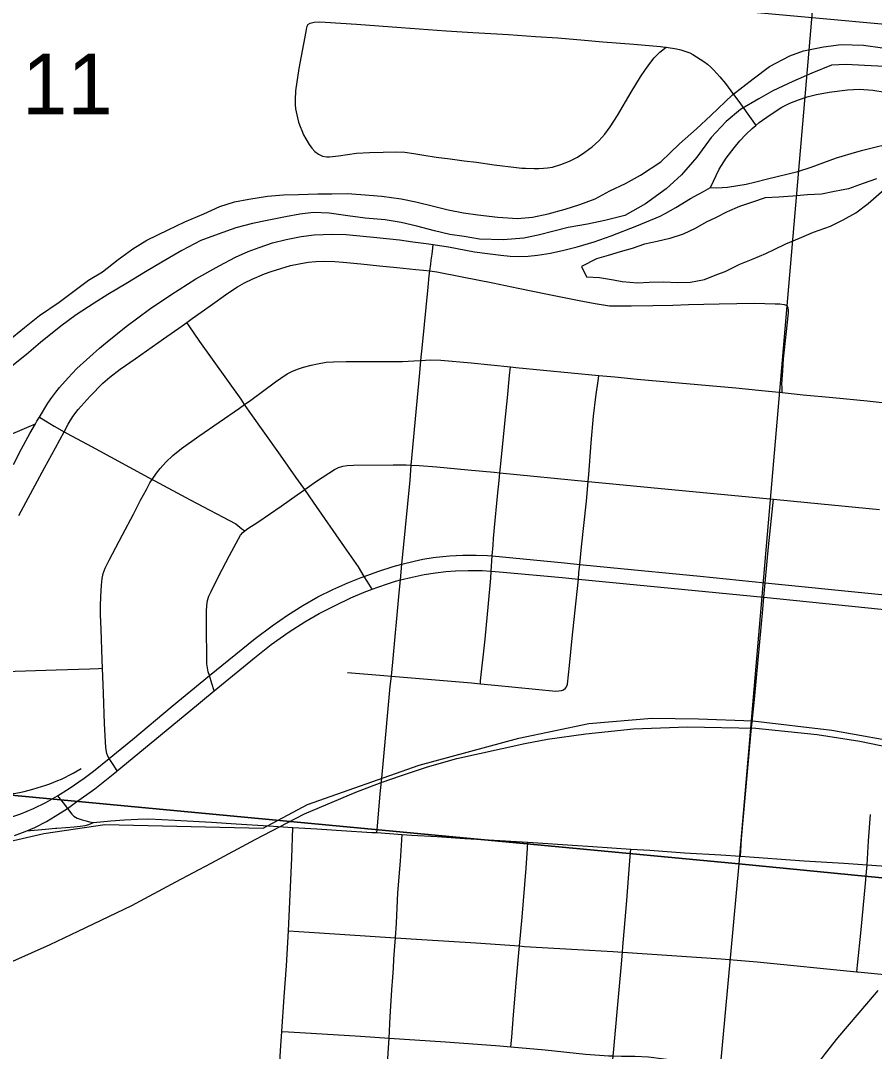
# Model space of a CAD drawing. Extents: x 0 to 1134, y 0 to 440.
# Drawn here: x 509.08 to 526.69, y 232.84 to 254.12 of the extents above; entities that cross this region are included whole.
import ezdxf

# ---------------------------------------------------------------- set-up
doc = ezdxf.new("R2010")
doc.units = 0
for name, color, linetype in [('Default', 7, 'Continuous'), ('GM_X_City_Street', 7, 'Continuous'), ('GM_X_County_Road', 7, 'Continuous'), ('GM_X_Major_River', 7, 'Continuous'), ('GM_X_Minor_Lake', 7, 'Continuous'), ('GM_X_Rail_Line', 7, 'Continuous'), ('GM_X_Section', 7, 'Continuous'), ('GM_X_Section_Text', 7, 'Continuous'), ('GM_X_State_Route', 7, 'Continuous'), ('GM_X_US_Route', 7, 'Continuous')]:
    doc.layers.add(name, color=color, linetype=linetype)

msp = doc.modelspace()

# ---------------------------------------------------------------- linework, layer by layer
at = {"layer": 'Default'}
for points in [[(539, 235.237), (539, 265.438), (526.475, 266.717), (523.893, 236.716)], [(539, 205.4), (539, 235.237), (523.893, 236.716), (521.182, 207.228)]]:
    msp.add_lwpolyline(points, close=True, dxfattribs=at)
at = {"layer": 'GM_X_City_Street'}
for points in [[(515.002, 254.042), (515.049, 254.066), (515.13, 254.086), (515.241, 254.096), (515.36, 254.088), (516.006, 254.046), (516.93, 253.978), (517.484, 253.937), (517.854, 253.91), (518.409, 253.875), (518.779, 253.854), (519.145, 253.832), (519.7, 253.795), (520.161, 253.763), (520.711, 253.721), (521.091, 253.684), (521.732, 253.637), (522.282, 253.585), (522.374, 253.576), (522.399, 253.572)], [(515.002, 254.042), (514.982, 254), (514.97, 253.945), (514.96, 253.894), (514.816, 253.132), (514.746, 252.671), (514.739, 252.485), (514.741, 252.392), (514.751, 252.299), (514.786, 252.116), (514.812, 252.027), (514.844, 251.939), (514.875, 251.852), (514.916, 251.763), (514.96, 251.679), (515.032, 251.563), (515.084, 251.487), (515.148, 251.419), (515.222, 251.364), (515.306, 251.325), (515.392, 251.308), (515.45, 251.311), (515.634, 251.331), (516.003, 251.382), (516.275, 251.396), (516.556, 251.405), (516.837, 251.41), (517.005, 251.405), (517.192, 251.381), (517.397, 251.346), (517.653, 251.304), (517.937, 251.265), (518.225, 251.228), (518.479, 251.196), (518.847, 251.142), (519.31, 251.087), (519.416, 251.078), (519.493, 251.075), (519.673, 251.068), (519.767, 251.068), (519.868, 251.073), (519.947, 251.08), (520.05, 251.097), (520.225, 251.148), (520.398, 251.218), (520.563, 251.304), (520.718, 251.406), (520.866, 251.517), (521.005, 251.641), (521.128, 251.78), (521.24, 251.929), (521.393, 252.163), (521.673, 252.644), (521.867, 252.959), (521.972, 253.112), (522.08, 253.262), (522.151, 253.351), (522.267, 253.47), (522.399, 253.572)], [(522.399, 253.572), (522.612, 253.536), (522.701, 253.516), (522.805, 253.487), (522.881, 253.457), (522.944, 253.425), (523.022, 253.376), (523.099, 253.326), (523.175, 253.276), (523.247, 253.222), (523.315, 253.162), (523.379, 253.099), (523.44, 253.032), (523.5, 252.962), (523.619, 252.826), (523.786, 252.599), (523.897, 252.451), (524.181, 252.044), (524.243, 251.955)], [(523.308, 250.679), (523.489, 251.053), (523.637, 251.284), (523.798, 251.496), (523.915, 251.643), (524.037, 251.768), (524.168, 251.891), (524.243, 251.955), (524.318, 252.019), (524.54, 252.177), (524.784, 252.332), (524.949, 252.419), (525.129, 252.488), (525.305, 252.547), (525.497, 252.594), (525.761, 252.646), (526.141, 252.693), (526.387, 252.703), (526.658, 252.683), (526.915, 252.646)], [(523.308, 250.679), (523.442, 250.667), (523.663, 250.682), (524.048, 250.746), (524.216, 250.785), (524.485, 250.852), (525.11, 251.009), (525.385, 251.096), (525.91, 251.286), (526.327, 251.412), (526.457, 251.449), (527.173, 251.624), (527.456, 251.671), (527.666, 251.69), (527.848, 251.69), (528.026, 251.688), (528.201, 251.685), (528.719, 251.641), (528.789, 251.635)], [(508.93, 244.961), (509.093, 245.284), (509.263, 245.598), (509.38, 245.798), (509.411, 245.852), (509.462, 245.936), (509.638, 246.227), (509.719, 246.342), (509.8, 246.451), (509.879, 246.55), (510.059, 246.747), (510.237, 246.937), (510.501, 247.183), (510.705, 247.358), (510.784, 247.427), (510.863, 247.494), (511.253, 247.81), (511.734, 248.167), (512.175, 248.461), (512.688, 248.789), (513.172, 249.058), (513.509, 249.24), (513.771, 249.358), (514, 249.44), (514.274, 249.531), (514.553, 249.605), (514.863, 249.662), (515.13, 249.699), (515.317, 249.709), (515.509, 249.711), (515.79, 249.704), (516.427, 249.644), (516.895, 249.593), (517.171, 249.556), (517.443, 249.519), (517.591, 249.498), (517.63, 249.493), (517.903, 249.45), (518.441, 249.35), (518.71, 249.312), (518.986, 249.277), (519.176, 249.26), (519.356, 249.255), (519.549, 249.26), (519.744, 249.277), (520.012, 249.324), (520.286, 249.381), (520.557, 249.452), (520.91, 249.558), (521.263, 249.679), (521.793, 249.886), (522.269, 250.086), (522.377, 250.14), (522.592, 250.264), (522.898, 250.446), (523.063, 250.54), (523.163, 250.593), (523.308, 250.679)], [(516.427, 237.36), (516.439, 237.491), (516.498, 238.159), (516.53, 238.486), (516.565, 238.858), (516.702, 240.374), (516.725, 240.592), (516.754, 240.878), (516.888, 242.307), (516.914, 242.579), (516.943, 242.901), (516.969, 243.168), (517.114, 244.633), (517.136, 244.947), (517.146, 245.088), (517.244, 246.121), (517.315, 246.854), (517.337, 247.105), (517.366, 247.431), (517.483, 248.621), (517.509, 248.852), (517.519, 248.954), (517.537, 249.093), (517.549, 249.179), (517.565, 249.302), (517.581, 249.423), (517.591, 249.498)], [(509.041, 243.906), (509.571, 244.892), (509.795, 245.301), (509.972, 245.634), (510.056, 245.793), (510.152, 245.95), (510.263, 246.096), (510.512, 246.372), (510.775, 246.636), (510.914, 246.759), (511.133, 246.929), (511.439, 247.141), (512.026, 247.555), (512.407, 247.823), (512.502, 247.891), (512.616, 247.974), (512.984, 248.235), (513.353, 248.492), (513.551, 248.623), (513.697, 248.708), (513.852, 248.786), (514.109, 248.895), (514.246, 248.941), (514.442, 249.007), (514.643, 249.063), (514.822, 249.102), (515.011, 249.135), (515.164, 249.148), (515.347, 249.155), (515.556, 249.148), (515.732, 249.133), (516.098, 249.098), (516.482, 249.061), (516.839, 249.022), (517.229, 248.983), (517.388, 248.967), (517.519, 248.954)], [(517.519, 248.954), (517.663, 248.934), (518.186, 248.83), (518.822, 248.71), (519.339, 248.599), (519.945, 248.473), (520.601, 248.344), (520.932, 248.283), (521.23, 248.237), (521.335, 248.231), (521.671, 248.235), (522.122, 248.244), (522.536, 248.25), (522.858, 248.259), (523.488, 248.274), (524.22, 248.287), (524.642, 248.278), (524.738, 248.272), (524.828, 248.26), (524.891, 248.24)], [(524.787, 246.443), (524.787, 246.546), (524.785, 246.616), (524.802, 246.893), (524.82, 247.138), (524.872, 247.642), (524.921, 248.09), (524.922, 248.143), (524.914, 248.188), (524.891, 248.24)], [(516.327, 242.384), (516.224, 242.553), (516.165, 242.65), (516.048, 242.844), (515.756, 243.262), (515.121, 244.178), (514.94, 244.441), (514.867, 244.543), (514.756, 244.696), (514.435, 245.148), (513.793, 246.058), (513.698, 246.198), (513.626, 246.304), (512.774, 247.498), (512.553, 247.818), (512.502, 247.891)], [(511.07, 238.638), (510.985, 238.768), (510.906, 238.889), (510.876, 238.935), (510.854, 238.992), (510.838, 239.072), (510.831, 239.12), (510.809, 239.607), (510.785, 240.241), (510.767, 240.752), (510.761, 240.928), (510.736, 241.562), (510.724, 241.853), (510.724, 242.034), (510.728, 242.236), (510.744, 242.471), (510.761, 242.608), (510.782, 242.712), (510.821, 242.822), (510.902, 242.984), (511.181, 243.505), (511.403, 243.933), (511.55, 244.22), (511.67, 244.443), (511.744, 244.579), (511.793, 244.652), (511.876, 244.777), (511.957, 244.874), (512.073, 245.006), (512.219, 245.145), (512.396, 245.291), (512.752, 245.543), (513.589, 246.124), (513.698, 246.198), (513.828, 246.286), (514.335, 246.664), (514.448, 246.741), (514.574, 246.829), (514.674, 246.881), (514.787, 246.926), (514.915, 246.966), (515.073, 247.008), (515.204, 247.035), (515.382, 247.068), (515.531, 247.081), (515.792, 247.084), (516.28, 247.087), (516.72, 247.087), (516.952, 247.087), (517.191, 247.097), (517.337, 247.105), (517.527, 247.116), (517.744, 247.11), (518.373, 247.055), (519.183, 246.972), (519.295, 246.961), (521.008, 246.797), (521.334, 246.765), (521.797, 246.722), (523.281, 246.59), (523.836, 246.538), (524.298, 246.493), (524.787, 246.443), (525.224, 246.398), (525.838, 246.341), (526.544, 246.273), (527.223, 246.197)], [(518.562, 240.432), (518.568, 240.496), (518.658, 241.352), (518.732, 242.089), (518.777, 242.611), (518.787, 242.754), (518.809, 243.071), (518.824, 243.292), (518.833, 243.431), (518.852, 243.659), (518.917, 244.304), (518.952, 244.627), (518.966, 244.788), (518.983, 244.974), (519.073, 245.875), (519.12, 246.337), (519.166, 246.799), (519.183, 246.972)], [(520.278, 240.306), (520.316, 240.342), (520.339, 240.371), (520.351, 240.401), (520.357, 240.427), (520.399, 240.809), (520.458, 241.371), (520.512, 241.89), (520.584, 242.593), (520.596, 242.722), (520.616, 242.895), (520.652, 243.256), (520.749, 244.199), (520.787, 244.609), (520.8, 244.755), (520.85, 245.403), (520.898, 245.957), (520.945, 246.358), (520.999, 246.732), (521.008, 246.797)], [(508.912, 245.597), (509.252, 245.744), (509.38, 245.798)], [(509.462, 245.936), (509.587, 245.86), (509.771, 245.747), (509.972, 245.634), (510.034, 245.6), (510.54, 245.328), (511.793, 244.652), (511.842, 244.625), (512.571, 244.227), (513.515, 243.735), (513.64, 243.634), (513.7, 243.587)], [(513.072, 240.287), (513.024, 240.44), (512.974, 240.6), (512.948, 240.682), (512.931, 240.76), (512.921, 240.844), (512.913, 241.694), (512.91, 241.931), (512.916, 242.047), (512.933, 242.154), (512.96, 242.244), (513.004, 242.338), (513.16, 242.647), (513.387, 243.078), (513.52, 243.334), (513.569, 243.423), (513.611, 243.497), (513.66, 243.557), (513.7, 243.587), (513.763, 243.635), (513.968, 243.77), (514.451, 244.102), (514.783, 244.333), (514.94, 244.441), (515.183, 244.612), (515.551, 244.858), (515.636, 244.9), (515.723, 244.926), (515.816, 244.936), (515.943, 244.943), (516.76, 244.95), (517.029, 244.952), (517.136, 244.947), (517.299, 244.938), (517.666, 244.908), (518.304, 244.847), (518.85, 244.799), (518.966, 244.788), (520.787, 244.609), (521.005, 244.588), (522.436, 244.448), (524.609, 244.243), (525.314, 244.177), (526.799, 244.028)], [(523.928, 236.871), (523.935, 236.985), (523.951, 237.234), (524.071, 238.618), (524.148, 239.454), (524.216, 240.111), (524.389, 241.963), (524.413, 242.218), (524.441, 242.519), (524.509, 243.26), (524.609, 244.243)], [(508.185, 240.561), (508.273, 240.576), (508.428, 240.612), (508.698, 240.682), (508.752, 240.684), (509.812, 240.72), (510.507, 240.743), (510.684, 240.749), (510.767, 240.752)], [(515.821, 240.663), (516.568, 240.606), (516.725, 240.592), (516.896, 240.578), (518.379, 240.449), (518.562, 240.432), (518.86, 240.402), (520.119, 240.282), (520.18, 240.286), (520.239, 240.296), (520.278, 240.306)], [(508.392, 238.312), (508.459, 238.293), (508.605, 238.251), (508.691, 238.222), (508.77, 238.197), (508.826, 238.18), (508.888, 238.167), (508.938, 238.166), (509.055, 238.189), (509.147, 238.208), (509.328, 238.257), (509.593, 238.339), (509.678, 238.369), (509.763, 238.401), (509.843, 238.434), (509.921, 238.467), (509.999, 238.505), (510.08, 238.546), (510.162, 238.59), (510.245, 238.637), (510.326, 238.686)], [(526.543, 236.694), (526.574, 237.19), (526.615, 237.733)], [(514.605, 235.331), (514.675, 236.833), (514.694, 237.468)], [(516.512, 230.678), (516.517, 230.74), (516.581, 231.538), (516.625, 232.279), (516.676, 233.015), (516.681, 233.116), (516.703, 233.556), (516.736, 234.116), (516.753, 234.38), (516.768, 234.565), (516.778, 234.748), (516.798, 235.016), (516.811, 235.19), (516.83, 235.49), (516.862, 236.119), (516.914, 236.772), (516.941, 237.214), (516.948, 237.324)], [(519.194, 232.941), (519.21, 233.137), (519.248, 233.597), (519.31, 234.332), (519.353, 234.882), (519.368, 235.021), (519.426, 235.617), (519.507, 236.629), (519.532, 237.038), (519.54, 237.161)], [(520.847, 226.488), (520.88, 227.438), (520.908, 228.008), (521.065, 229.943), (521.088, 230.243), (521.114, 230.593), (521.173, 231.335), (521.236, 231.984), (521.302, 232.75), (521.308, 232.818), (521.391, 233.739), (521.467, 234.572), (521.494, 234.891), (521.502, 235.006), (521.53, 235.322), (521.581, 235.96), (521.619, 236.423), (521.655, 236.869), (521.667, 237.021)], [(526.33, 234.487), (526.344, 234.621), (526.422, 235.357), (526.512, 236.309), (526.532, 236.554), (526.543, 236.694)], [(514.313, 230.776), (514.317, 230.863), (514.337, 231.287), (514.379, 231.938), (514.404, 232.308), (514.446, 232.959), (514.466, 233.258), (514.515, 233.97), (514.561, 234.613), (514.605, 235.331)], [(514.605, 235.331), (515.24, 235.295), (516.811, 235.19), (517.354, 235.153), (518.467, 235.084), (519.368, 235.021), (519.475, 235.013), (520.566, 234.95), (521.303, 234.904), (521.494, 234.891), (523.531, 234.757), (524.273, 234.693), (526.33, 234.487), (526.354, 234.485), (527.04, 234.417)], [(514.466, 233.258), (514.6, 233.248), (515.069, 233.218), (516.088, 233.16), (516.681, 233.116), (517.846, 233.043), (518.505, 232.996), (518.961, 232.959), (519.194, 232.941), (519.896, 232.876), (520.729, 232.788), (521.116, 232.758), (521.205, 232.754), (521.302, 232.75), (521.473, 232.748), (521.752, 232.747), (522.03, 232.729), (522.677, 232.653), (522.867, 232.629)]]:
    msp.add_lwpolyline(points, dxfattribs=at)
at = {"layer": 'GM_X_County_Road'}
for p, q in [((516.427, 237.36), (516.948, 237.324)), ((526.576, 233.873), (526.769, 234.099))]:
    msp.add_line(p, q, dxfattribs=at)
for points in [[(509.84, 238.119), (509.952, 237.976), (510.042, 237.861)], [(510.042, 237.861), (510.135, 237.742), (510.174, 237.703), (510.207, 237.678), (510.242, 237.66), (510.284, 237.644), (510.347, 237.623), (510.429, 237.602), (510.5, 237.586), (510.58, 237.567)], [(509.203, 237.398), (509.587, 237.431), (509.794, 237.449)], [(509.794, 237.449), (509.824, 237.451), (510.011, 237.467), (510.183, 237.48), (510.305, 237.493), (510.408, 237.509), (510.482, 237.53), (510.58, 237.567)], [(510.58, 237.567), (510.936, 237.604), (511.219, 237.626), (511.497, 237.641), (511.724, 237.647), (512.255, 237.62), (513.011, 237.573), (513.521, 237.544), (514.19, 237.501), (514.694, 237.468)], [(514.694, 237.468), (515.186, 237.438), (515.699, 237.404), (516.325, 237.366), (516.427, 237.36)], [(516.948, 237.324), (517.142, 237.311), (517.668, 237.277), (518.239, 237.242), (518.728, 237.211), (519.54, 237.161)], [(519.54, 237.161), (519.642, 237.155), (520.464, 237.1), (520.884, 237.073), (521.667, 237.021)], [(521.667, 237.021), (522.06, 236.997), (522.776, 236.946), (523.527, 236.899), (523.928, 236.871)], [(523.928, 236.871), (525.24, 236.779), (526.064, 236.727), (526.543, 236.694)], [(526.543, 236.694), (526.83, 236.674), (527.954, 236.59), (528.453, 236.564), (528.631, 236.555)], [(523.788, 229.916), (524.501, 231.043), (524.797, 231.521), (525.157, 232.069), (525.355, 232.36), (525.685, 232.804), (525.937, 233.124), (526.576, 233.873)]]:
    msp.add_lwpolyline(points, dxfattribs=at)
at = {"layer": 'GM_X_Major_River'}
for points in [[(508.817, 247.512), (509.154, 247.789), (509.467, 248.033), (509.873, 248.308), (510.174, 248.54), (510.476, 248.761), (510.764, 248.937), (511.089, 249.192), (511.391, 249.413), (511.68, 249.588), (512.117, 249.806), (512.463, 249.969), (512.854, 250.131), (513.188, 250.282), (513.486, 250.378), (513.784, 250.439), (514.172, 250.499), (514.503, 250.525), (514.811, 250.529), (515.209, 250.543), (515.494, 250.547), (515.813, 250.551), (516.097, 250.533), (516.529, 250.5), (516.927, 250.445), (517.232, 250.381), (517.595, 250.292), (517.9, 250.217), (518.217, 250.152), (518.513, 250.111), (518.921, 250.067), (519.331, 250.035), (519.639, 250.062), (519.959, 250.134), (520.314, 250.228), (520.613, 250.324), (520.934, 250.442), (521.234, 250.606), (521.557, 250.758), (521.868, 250.933), (522.285, 251.208), (522.67, 251.575), (523.019, 251.886), (523.321, 252.164), (523.764, 252.587), (524.193, 252.919), (524.53, 253.173), (524.945, 253.391), (525.232, 253.498), (525.644, 253.58), (526.009, 253.628), (526.465, 253.617), (526.862, 253.562)], [(526.898, 253.174), (526.489, 253.195), (526.113, 253.215), (525.806, 253.2), (525.403, 253.038), (525.012, 252.865), (524.597, 252.67), (524.309, 252.505), (523.928, 252.286), (523.637, 252.042), (523.322, 251.708), (523.027, 251.304), (522.711, 250.936), (522.397, 250.647), (521.968, 250.337), (521.541, 250.097), (521.129, 249.992), (520.774, 249.921), (520.374, 249.851), (520.076, 249.778), (519.755, 249.694), (519.458, 249.633), (519.035, 249.597), (518.546, 249.609), (518.228, 249.662), (517.933, 249.703), (517.616, 249.779), (517.254, 249.879), (516.926, 249.955), (516.597, 250.008), (516.188, 250.041), (515.825, 250.095), (515.439, 250.149), (515.12, 250.157), (514.835, 250.129), (514.538, 250.068), (514.16, 249.997), (513.863, 249.936), (513.519, 249.841), (513.151, 249.713), (512.795, 249.585), (512.403, 249.377), (511.988, 249.136), (511.653, 248.939), (511.283, 248.708), (510.878, 248.467), (510.59, 248.291), (510.219, 248.049), (509.906, 247.817), (509.488, 247.474), (509.198, 247.23), (508.757, 246.875)]]:
    msp.add_lwpolyline(points, dxfattribs=at)
at = {"layer": 'GM_X_Minor_Lake'}
for points in [[(526.736, 250.858), (526.463, 250.758), (526.156, 250.646), (525.872, 250.592), (525.599, 250.537), (525.315, 250.527), (525.008, 250.495), (524.724, 250.475), (524.441, 250.466), (524.179, 250.376), (523.906, 250.287), (523.655, 250.175), (523.416, 250.052)], [(525.924, 249.946), (526.049, 250.01), (526.311, 250.156), (526.562, 250.347), (527.11, 250.821)], [(523.416, 250.052), (523.222, 249.962), (522.994, 249.827), (522.744, 249.715), (522.471, 249.626), (522.209, 249.56), (521.948, 249.505), (521.697, 249.416), (521.447, 249.349), (521.197, 249.271), (520.958, 249.205), (520.65, 249.048)], [(520.65, 249.048), (520.751, 248.831), (521.023, 248.817), (521.306, 248.77), (521.488, 248.734), (521.805, 248.709), (522.044, 248.719), (522.339, 248.728), (522.634, 248.714), (522.895, 248.724), (523.19, 248.778), (523.441, 248.879), (523.612, 248.946), (523.919, 249.092), (524.192, 249.204), (524.454, 249.315), (524.625, 249.394), (524.864, 249.517), (525.149, 249.629), (525.434, 249.752), (525.787, 249.875), (525.924, 249.946)]]:
    msp.add_lwpolyline(points, dxfattribs=at)
at = {"layer": 'GM_X_Rail_Line'}
for points in [[(508.347, 256.739), (508.502, 256.582), (508.719, 256.415), (509.614, 255.938), (511.111, 255.517), (514.079, 255.189), (523.82, 254.329), (528.655, 253.89), (531.19, 253.587), (539, 252.082)], [(489.581, 235.772), (508.236, 237.037), (509.552, 237.341), (510.814, 237.527), (514.082, 237.454), (514.997, 237.938), (517.299, 238.756), (519.354, 239.313), (520.803, 239.61), (522.102, 239.722), (523.062, 239.706), (524.185, 239.666), (525.815, 239.475), (527.43, 239.188), (528.51, 238.926), (536.834, 236.084), (539, 235.883)], [(508.079, 234.337), (509.688, 235.054), (510.265, 235.323), (511.37, 235.854), (512.278, 236.341), (513.005, 236.731), (513.914, 237.22), (514.934, 237.745), (515.994, 238.192), (516.513, 238.393), (516.935, 238.537), (517.473, 238.716), (518.079, 238.889), (519.482, 239.203), (519.944, 239.291), (520.736, 239.4), (521.724, 239.5), (522.837, 239.546), (524.243, 239.515), (525.512, 239.385), (526.395, 239.245), (527.495, 239.02)]]:
    msp.add_lwpolyline(points, dxfattribs=at)
at = {"layer": 'GM_X_Section'}
for points in [[(496.343, 269.642), (526.475, 266.717), (523.893, 236.716), (493.567, 239.575)], [(493.567, 239.575), (523.893, 236.716), (521.182, 207.228), (490.882, 209.496)]]:
    msp.add_lwpolyline(points, close=True, dxfattribs=at)
at = {"layer": 'GM_X_State_Route'}
for p, q in [((520.584, 242.593), (524.413, 242.218)), ((509.79, 237.702), (510.042, 237.861))]:
    msp.add_line(p, q, dxfattribs=at)
for points in [[(516.914, 242.579), (517.154, 242.633), (517.401, 242.685), (517.634, 242.721), (517.851, 242.747), (518.046, 242.762), (518.307, 242.771), (518.597, 242.768), (518.787, 242.754)], [(516.327, 242.384), (516.444, 242.427), (516.643, 242.498), (516.811, 242.549), (516.914, 242.579)], [(518.787, 242.754), (519.032, 242.735), (520.252, 242.626), (520.584, 242.593)], [(513.072, 240.287), (513.901, 240.968), (514.247, 241.243), (514.617, 241.506), (514.94, 241.714), (515.236, 241.882), (515.565, 242.051), (515.887, 242.205), (516.163, 242.321), (516.327, 242.384)], [(524.413, 242.218), (525.354, 242.125), (527.101, 241.945), (528.513, 241.817), (529.422, 241.723), (529.637, 241.7)], [(511.07, 238.638), (512.547, 239.854), (513.072, 240.287)], [(510.042, 237.861), (510.211, 237.983), (510.605, 238.267), (511.052, 238.623), (511.07, 238.638)], [(509.203, 237.398), (509.367, 237.467), (509.613, 237.592), (509.79, 237.702)], [(508.948, 237.304), (509.113, 237.361), (509.203, 237.398)]]:
    msp.add_lwpolyline(points, dxfattribs=at)
at = {"layer": 'GM_X_US_Route'}
for p, q in [((520.584, 242.593), (524.413, 242.218)), ((509.79, 237.702), (510.042, 237.861))]:
    msp.add_line(p, q, dxfattribs=at)
for points in [[(510.577, 238.63), (510.906, 238.889), (511.057, 239.013), (511.386, 239.283), (512.204, 239.969), (512.974, 240.6), (513.913, 241.364), (514.266, 241.632), (514.583, 241.85), (514.897, 242.047), (515.21, 242.225), (515.518, 242.382), (515.825, 242.514), (516.105, 242.628), (516.165, 242.65), (516.446, 242.751), (516.761, 242.851), (516.943, 242.901), (517.196, 242.966), (517.375, 243.002), (517.587, 243.036)], [(517.587, 243.036), (517.648, 243.046), (517.924, 243.075), (518.2, 243.09), (518.477, 243.09), (518.712, 243.08), (518.809, 243.071), (520.298, 242.926), (520.616, 242.895), (521.249, 242.834), (523.098, 242.654), (524.441, 242.519), (526.702, 242.291), (529.283, 242.031), (529.668, 241.988)], [(516.914, 242.579), (517.154, 242.633), (517.401, 242.685), (517.634, 242.721), (517.851, 242.747), (518.046, 242.762), (518.307, 242.771), (518.597, 242.768), (518.787, 242.754)], [(516.327, 242.384), (516.444, 242.427), (516.643, 242.498), (516.811, 242.549), (516.914, 242.579)], [(518.787, 242.754), (519.032, 242.735), (520.252, 242.626), (520.584, 242.593)], [(513.072, 240.287), (513.901, 240.968), (514.247, 241.243), (514.617, 241.506), (514.94, 241.714), (515.236, 241.882), (515.565, 242.051), (515.887, 242.205), (516.163, 242.321), (516.327, 242.384)], [(524.413, 242.218), (525.354, 242.125), (527.101, 241.945), (528.513, 241.817), (529.422, 241.723), (529.637, 241.7)], [(511.07, 238.638), (512.547, 239.854), (513.072, 240.287)], [(508.408, 237.545), (508.543, 237.577), (508.814, 237.656), (509.081, 237.748), (509.342, 237.856), (509.595, 237.981), (509.84, 238.119), (510.08, 238.269), (510.389, 238.483), (510.577, 238.63)], [(510.042, 237.861), (510.211, 237.983), (510.605, 238.267), (511.052, 238.623), (511.07, 238.638)], [(509.203, 237.398), (509.367, 237.467), (509.613, 237.592), (509.79, 237.702)], [(508.948, 237.304), (509.113, 237.361), (509.203, 237.398)]]:
    msp.add_lwpolyline(points, dxfattribs=at)

# ---------------------------------------------------------------- texts
at = {"layer": 'GM_X_Section_Text'}
msp.add_text('11', height=1.2557, rotation=0, dxfattribs=at).set_placement((509.106, 252.186))

doc.saveas('drawing.dxf')
